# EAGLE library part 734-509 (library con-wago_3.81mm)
Serie 734, Federleiste mit geraden Einlötstiften / Series 734, Female connector with straight solder pins Polzahl / Pole No.: 9 Bemessungsspannung / Rated Voltage: 160 V Nennstrom / Nominal Current: 10 A Lötstiftlänge: / Solder Pin Length: 3.8 mm Farbe / Color: orange / orange Stand: 01.01.2012. Die jeweils aktuellen Daten zu diesem Artikel finden Sie in unserem Produktkatalog, den Sie unter www.wago.com einsehen können. As of: 01/01/2012. Please find the newest data for this article in our product catalogue, which can be viewed under www.wago.com.
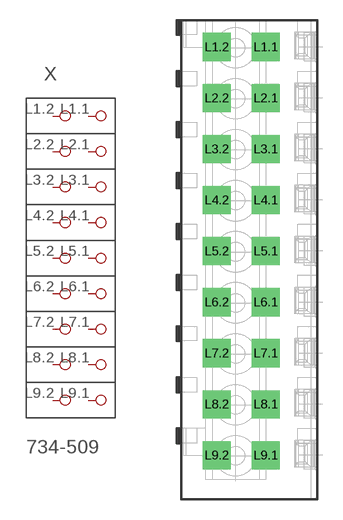
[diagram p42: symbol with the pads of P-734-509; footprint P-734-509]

Designator prefix X

## 734-509  [P-734-509]
L1.1  P1.1
L1.2  P1.2
L2.1  P2.1
L2.2  P2.2
L3.1  P3.1
L3.2  P3.2
L4.1  P4.1
L4.2  P4.2
L5.1  P5.1
L5.2  P5.2
L6.1  P6.1
L6.2  P6.2
L7.1  P7.1
L7.2  P7.2
L8.1  P8.1
L8.2  P8.2
L9.1  P9.1
L9.2  P9.2

## Footprint P-734-509 (pad centres in mm)
drill 1.4 square: L1.1 1.207,15.885; L1.2 -2.443,15.885; L2.1 1.207,12.075; L2.2 -2.443,12.075; L3.1 1.207,8.265; L3.2 -2.443,8.265; L4.1 1.207,4.455; L4.2 -2.443,4.455; L5.1 1.207,0.645; L5.2 -2.443,0.645; L6.1 1.207,-3.165; L6.2 -2.443,-3.165; L7.1 1.207,-6.975; L7.2 -2.443,-6.975; L8.1 1.207,-10.785; L8.2 -2.443,-10.785; L9.1 1.207,-14.595; L9.2 -2.443,-14.595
